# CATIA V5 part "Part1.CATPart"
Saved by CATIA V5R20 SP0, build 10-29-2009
Part number: jambe1
Bounding box of the stored display mesh (mm): x 225 to 325, y -1070 to -40, z 10 to 40
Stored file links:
  D:\Dropbox\Pack 1 sylvain\mmoreau\mmoreau\mmoreau\fin\Part1.CATPart
  U:\think motion\fin\think motion2.CATProduct
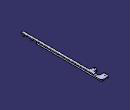
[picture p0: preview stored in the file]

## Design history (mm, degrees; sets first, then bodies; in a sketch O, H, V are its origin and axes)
External parameters (linked from other documents)
  `External.longueur jambe` = 1000 mm
  External.V = -14 mm
Set1
  Plane1: linked copy from another document
  Line1: linked copy from another document
  Line2: linked copy from another document
  Point1: linked copy from another document
  Point2: linked copy from another document
  Line3: linked copy from another document
  Plane2: linked copy from another document
Body1 (main body)
  Sketch1 on Plane1, origin (325, 0, 0), H (0, 1, 0), V (0, 0, 1)
    point P1 (-1070, 40)
    line L1 (-40, 30) -> (-40, 10)
    line L2 (-40, 10) -> (-1070, 10)
    line L3 (-1070, 10) -> (-1070, 40)
    reference projected line E1 (-70, 10) -> (-70, 50) from Line2
    reference projected point E4 (-70, 30) from Point1
    line L4 (-40, 30) -> (-140, 30)
    point P5 (-140, 30)
    line L5 (-140, 30) -> (-145.7735, 40)
    line L6 (-145.7735, 40) -> (-1070, 40)
    point P7 (-1070, 40)
    reference projected line E5 (-1070, 30) -> (-70, 30) from Line1
    distance L1 E1 = 30
    distance E4 L3 = 1000 {= `External.longueur jambe`}
    distance L2 L6 = 30
    distance L1 P5 = 100
    distance L6 E5 = 10
    angle L5 L4 = 120
    distance L4 L2 = 20
    horizontal: L2 H, L4 H, L6 H
    vertical: L1 V, L3 V
    coincidence: P1 P7
  Pad1: profile Sketch1, direction (-1, 0, 0), length 40
  Sketch2 on face of Pad1 from Sketch1.L2, origin (0, 0, 10), H (1, 0, 0), V (0, -1, 0)
    line L1 (225, 110) -> (325, 110)
    line L2 (325, 110) -> (325, 40)
    line L3 (325, 40) -> (225, 40)
    line L4 (225, 40) -> (225, 110)
    reference projected line E1 (325, 1070) -> (325, 40) from edge [face of Pad1 from Sketch1.L2 | start face of Pad1]
    reference projected line E2 (325, 40) -> (285, 40) from edge [face of Pad1 from Sketch1.L2 | face of Pad1 from Sketch1.L1]
    distance L4 L2 = 100
    distance L1 L3 = 70
    horizontal: L1 H, L3 H
    vertical: L2 V, L4 V
    coincidence: E1 L2, L3 E2
  Pad2: profile Sketch2, direction (0, 0, 1), length 20
  Sketch3 on face of Pad2, origin (282.6578, -85.8937, 10), H (1, 0, 0), V (0, -1, 0)
    point P1 (-32.6578, -15.8937)
    reference projected point E1 (-32.6578, -15.8937) from Point1
    coincidence: E1 P1
  Hole1: placed by Sketch3, at (250, -70, 10) direction (0, 0, 1), diameter 10, through (limit type 3)
  Fillet1: radius 20, on edge [face of Pad2 from Sketch2.L1 | end face of Pad1]; edge [face of Pad2 from Sketch2.L1 | face of Pad2 from Sketch2.L4]; edge [face of Pad2 from Sketch2.L4 | face of Pad2]; edge [face of Pad2 | face of Pad2]
  Sketch4 on face of Pad2, origin (325, 0, 0), H (0, 1, 0), V (0, 0, 1)
    line L1 (-1070, 35) -> (-870, 35)
    line L2 (-870, 35) -> (-870, -84.0912)
    line L3 (-870, -84.0912) -> (-1070, -84.0912)
    line L4 (-1070, -84.0912) -> (-1070, 35)
    reference projected line E1 (-1070, 40) -> (-1070, 10) from edge [face of Pad1 from Sketch1.L3 | face of Pad2]
    reference projected line E2 (-145.7735, 40) -> (-1070, 40) from edge [face of Pad1 from Sketch1.L6 | start face of Pad1]
    distance L2 L4 = 200
    distance L1 E2 = 5
    horizontal: L1 H, L3 H
    vertical: L2 V, L4 V
    coincidence: L4 E1
  Pocket1: profile Sketch4, direction (-1, 0, 0), length 35
  Sketch5 on end face of Pocket1, origin (290, 0, 0), H (0, 1, 0), V (0, 0, 1)
    circle A1 centre (-1035, 16) radius 4
    point P1 (-1035, 16)
    circle A2 centre (-935, 16) radius 4
    point P2 (-935, 16)
    reference projected line E1 (-1070, 35) -> (-1070, 10) from edge [face of Pad1 from Sketch1.L3 | end face of Pocket1]
    reference projected line E2 (-1070, 30) -> (-70, 30) from Line1
    reference projected line E3 (-1070, 30) -> (-70, 30) from Line1
    radius A2 = 4
    radius A1 = 4
    distance P1 P2 = 100
    distance P1 E1 = 35
    distance P1 E2 = -14 {= External.V}
    distance P2 E3 = -14 {= Sketch5.distance(P1 E2)}
  Pad3: profile Sketch5, direction (1, 0, 0), length 35
  Fillet2: radius 20, on edge [face of Pad2 | face of Pad1 from Sketch1.L5]
  Fillet3: radius 20, on edge [face of Pocket1 from Sketch4.L2 | end face of Pocket1]
  Sketch6 on face of Pad1 from Sketch1.L6, origin (0, 0, 40), H (1, 0, 0), V (0, 1, 0)
    arc A1 centre (250, -200) radius 20 from (246.527, -180.3038) to (246.527, -219.6962) ccw
    point P1 (250, -200)
    reference projected point E1 (250, -200) from Point2
    line L1 (246.527, -180.3038) -> (285, -173.52)
    point P3 (285, -173.52)
    line L2 (246.527, -219.6962) -> (285, -226.48)
    point P5 (285, -226.48)
    reference intersected line E2 (285, -1070) -> (285, -145.7735) from end face of Pad1
    reference intersected line E3 (285, -1070) -> (285, -145.7735) from end face of Pad1
    reference projected line E4 (245, -200) -> (250, -200) from Line3
    reference projected line E5 (245, -200) -> (250, -200) from Line3
    line L3 (285, -173.52) -> (285, -226.48)
    radius A1 = 20
    angle E4 L1 = 10
    coincidence: E1 P1, P3 E2, E3 P5
    tangency: L1 A1, L2 A1
    symmetry: L2 L1 E5
    vertical: L3 V
  Pad4: profile Sketch6, direction (0, 0, -1), length 30
  Sketch7 on face of Pad4, origin (262.794, -196.0753, 40), H (1, 0, 0), V (0, 1, 0)
    point P1 (-12.794, -3.9247)
    reference projected point E1 (-12.794, -3.9247) from Point2
    coincidence: E1 P1
  Hole2: placed by Sketch7, at (250, -200, 40) direction (0, 0, -1), diameter 10, through (limit type 3)
  Sketch8 on Plane2, origin (250, 0, 0), H (0, 1, 0), V (0, 0, 1)
    line L1 (-230, 35) -> (-170, 35)
    line L2 (-170, 35) -> (-170, 19)
    line L3 (-170, 19) -> (-230, 19)
    line L4 (-230, 19) -> (-230, 35)
    reference projected point E1 (-200, 30) from Point2
    reference projected point E2 (-200, 30) from Point2
    reference projected point E3 (-200, 30) from Point2
    distance E1 L2 = 30
    distance L4 E2 = 30
    distance L1 E3 = 5
    distance L3 L1 = 16
    horizontal: L1 H, L3 H
    vertical: L2 V, L4 V
  Pocket2: profile Sketch8, direction (-1, 0, 0), length 30, mirrored extent
  Fillet4: radius 5, on edge [face of Pad4 | face of Pad2] (x2); edge [end face of Pad1 | face of Pad4] (x2)
  Fillet5: radius 2, on face of Pad1 from Sketch1.L3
